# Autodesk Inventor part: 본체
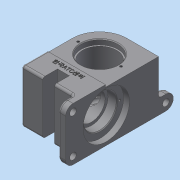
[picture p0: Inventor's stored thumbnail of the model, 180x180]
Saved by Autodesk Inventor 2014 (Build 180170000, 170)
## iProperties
Created: 2023-09
Part Number: 본체
Material: 일반
Document SubType Name: Modeling
Designer: dg
Density: 1 g/cm^3
Appearance: 기본값
Author: dg
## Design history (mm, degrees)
sketch "스케치1"
  geometry: L1 (0, 0)-(80, 0); L2 (80, 0)-(80, 106); L3 (80, 106)-(0, 106); L4 (0, 106)-(0, 0)
  constraints: 8 end point, 2 perpendicular, 1 horizontal, 1 parallel
  dimensions: "d0" = 80 distance of L2.end L3.end; "d1" = 106 distance of L3.end L1.start
extrude "돌출1" new body sketch "스케치1" distance "d2" = 33; taper "d3" = 0 deg; dims "d119" = 36, "d120" = 0
fillet "모깎기1" dims "d4" = 37
sketch "스케치2"
  geometry: L1 (80, 0)-(80, 106) reference; L2 (80, 106)-(37, 106) reference; L3 (0, 0)-(80, 0); L4 (80, 0)-(80, 34); L5 (80, 34)-(0, 34); L6 (0, 34)-(0, 0)
  constraints: 8 end point, 2 parallel, 1 horizontal, 1 perpendicular, 1 point on line
  dimensions: "d5" = 72 distance between parallel lines of L2 L5
extrude "돌출2" join sketch "스케치2" distance "d6" = 3; taper "d7" = 0 deg
sketch "스케치3"
  geometry: L1 (0, 0)-(-72, 0); L2 (-72, 0)-(-72, -20); L3 (-72, -20)-(0, -20); L4 (0, -20)-(0, 0); L5 (0, 106)-(-20, 106); L6 (-20, 106)-(-20, 126); L7 (-20, 126)-(0, 126); L8 (0, 126)-(0, 106); 2 further points
  constraints: 16 end point, 4 parallel, 2 horizontal, 2 perpendicular, 1 coincident
  dimensions: "d8" = 20 distance of L1.end L2.end; "d18" = 20 distance of L6.end L7.end; "d19" = 146 distance between parallel lines of L3 L7
extrude "돌출3" join sketch "스케치3" distance "d9" = 10; taper "d10" = 0 deg
sketch "스케치4"
  geometry: L1 (37, 106)-(80, 106) reference; L2 (80, 106)-(80, -20) reference; L3 (80, -20)-(70, -20) reference; L4 (70, -20)-(70, 0) reference; L5 (70, 0)-(0, 0) reference; L6 (0, 0)-(0, 69) reference; L7 (0, 35)-(80, 35); L8 (3, 66.5)-(3, 57.5); L9 (3, 57.5)-(15, 57.5); L10 (15, 57.5)-(15, 53.5); L11 (15, 53.5)-(60, 53.5); L12 (60, 53.5)-(60, 57.5); L13 (72, 57.5)-(72, 66.5); L14 (3, 66.5)-(0, 66.5); L15 (72, 66.5)-(80, 66.5); L16 (60, 57.5)-(72, 57.5); A1 r 37 centre (37, 69) between (37, 106) and (0, 69) reference
  constraints: 20 end point, 4 parallel, 4 point on line, 2 horizontal alignment, 2 perpendicular, 1 collinear, 1 vertical
  dimensions: "d11" = 35 distance between parallel lines of L5 L7; "d13" = 12 distance of L8.end L9.end; "d15" = 45 diameter of L9 L7; "d16" = 37 diameter of L11 L7; "d37" = 3 distance of L8.start L14.end; "d38" = 8 distance of L13.end L15.end; "d39" = 63 diameter of L15 L7; "d121" = 12 distance of L12.end L13.start
revolve "회전1" sketch "스케치4" stored, may be unused: angle "d17" = 90 deg
extrude "돌출4" join sketch "스케치3" distance "d20" = 10; taper "d21" = 0 deg
fillet "모깎기2" dims "d22" = 10
node "작업 평면1"
sketch "스케치5"
  geometry: L1 (-3, 0)-(0, 0) reference; L2 (0, 0)-(0, 72) reference; L3 (0, 72)-(69, 72) reference; L4 (69, 72)-(69, -34) reference; L5 (69, -34)-(-3, -34) reference; L6 (-3, -34)-(-3, 0) reference; L7 (0, 35)-(66, 35); L8 (0, 60)-(7, 60); L9 (7, 60)-(7, 58); L10 (7, 58)-(47, 58); L11 (47, 58)-(47, 52.5); L12 (47, 52.5)-(62, 52.5); L13 (62, 52.5)-(62, 50.5); L14 (62, 50.5)-(66, 50.5); L15 (66, 50.5)-(66, 35); C1 r 18.5 at (33, 1) reference; 1 further point
  constraints: 18 end point, 7 parallel, 2 perpendicular, 2 point on line
  dimensions: "d24" = 69 distance between parallel lines of L5 L7; "d25" = 66 distance of L7.start L7.end; "d26" = 7 distance of L8.start L8.end; "d27" = 40 distance of L9.end L10.end; "d28" = 15 distance of L11.end L12.end; "d29" = 50 diameter of L8 L7; "d30" = 46 diameter of L10 L7; "d31" = 35 diameter of L12 L7; "d32" = 31 diameter of L14 L7
revolve "회전2" sketch "스케치5" stored, may be unused: angle "d33" = 90 deg
chamfer "모따기1" distance "d34" = 1; stored, may be unused: second distance "d35" = 2, angle "d36" = 45 deg
chamfer "모따기2" distance "d41" = 1; stored, may be unused: second distance "d42" = 2, angle "d43" = 45 deg
fillet "모깎기3" dims "d44" = 0.3
fillet "모깎기4" dims "d45" = 4
fillet "모깎기5" dims "d46" = 10
hole "구멍1" diameter "d49" = 9; stored, may be unused: countersink angle "d53" = 90 deg, drill point angle "d55" = 118 deg; dims "d47" = 10, "d48" = 10, "d50" = 6, "d51" = 4, "d52" = 2, "d54" = 8
hole "구멍2" diameter "d58" = 9; stored, may be unused: countersink angle "d62" = 90 deg, drill point angle "d64" = 118 deg; dims "d56" = 10, "d57" = 10, "d59" = 6, "d60" = 4, "d61" = 2, "d63" = 8
hole "구멍3" diameter "d67" = 9; stored, may be unused: countersink angle "d71" = 90 deg, drill point angle "d73" = 118 deg; dims "d65" = 10, "d66" = 10, "d68" = 6, "d69" = 4, "d70" = 2, "d72" = 8
sketch "스케치6"
  geometry: C1 r 31.5 at (0, 0) reference; 2 further points
  constraints: 1 vertical alignment
  dimensions: "d74" = 26 distance of C1.centre point (0, 26)
hole "구멍4" sketch "스케치6" at (0, 26) diameter "d75" = 3.242; stored, may be unused: countersink angle "d79" = 90 deg, drill point angle "d81" = 118 deg; dims "d76" = 8, "d77" = 4, "d78" = 2, "d80" = 10
node "작업 평면2"
sketch "스케치7"
  geometry: A1 r 37 centre (37, 69) between (37, 106) and (0, 69) reference; 3 further points
  constraints: 2 horizontal alignment
  dimensions: "d85" = 58 distance of point (66, 69) point (8, 69); "d86" = 29 distance of A1.centre point (8, 69)
hole "구멍5" sketch "스케치7" at (8, 69), (66, 69) diameter "d87" = 3.242; stored, may be unused: countersink angle "d91" = 90 deg, drill point angle "d93" = 118 deg; dims "d88" = 8, "d89" = 4, "d90" = 2, "d92" = 10
sketch "스케치8"
  geometry: L1 (0, 0)-(70, 0) reference; L2 (29, 0)-(45, 0); L3 (45, 0)-(45, 20); L4 (45, 20)-(29, 20); L5 (29, 20)-(29, 0); C1 r 11.5 at (37, 69) reference; 2 further points
  constraints: 8 end point, 2 parallel, 1 horizontal, 1 midpoint, 1 perpendicular, 1 point on line, 1 vertical alignment
  dimensions: "d94" = 16 distance of L3.end L4.end; "d95" = 20 distance of L2.end L3.end
extrude "돌출5" cut sketch "스케치8" stored distance "d97" = 10; taper "d98" = 0 deg
sketch "스케치9"
  geometry: L1 (8, -3)-(8, -72) reference; L2 (0, -46.828)-(16, -46.828) reference; L3 (0, -46.828)-(0, -72) reference; L4 (16, -72)-(0, -72) reference; L5 (16, -46.828)-(16, -72) reference; L6 (8, -72)-(41, -72) reference; 4 further points
  constraints: 3 point on line
  dimensions: "d101" = 35 distance from line of L6 point (8, -37); "d102" = 25 distance of point (8, -12) point (8, -37); "d103" = 25 distance of point (8, -62) point (8, -37)
hole "구멍6" sketch "스케치9" at (8, -12), (8, -62) diameter "d104" = 3.242; stored, may be unused: countersink angle "d108" = 90 deg, drill point angle "d110" = 118 deg; dims "d105" = 8, "d106" = 4, "d107" = 2, "d109" = 10
sketch "스케치10"
  geometry: L1 (0, 0)-(29, 0) reference; C1 r 11.5 at (37, 69) reference; 1 further point
  constraints: 1 vertical alignment, 1 other
  dimensions: "d111" = 27 distance from line of L1 point (37, 27)
feature "엠보싱1" sketch "스케치10" dims "d0" = 80, "d1" = 106, "d7" = 0, "d112" = 0.5, "d113" = 0
fillet "모깎기6" dims "d114" = 3
fillet "모깎기7" dims "d115" = 3
fillet "모깎기8" dims "d116" = 3
fillet "모깎기9" dims "d117" = 3
fillet "모깎기10" dims "d118" = 3
fillet "모깎기11" dims "d122" = 3
fillet "모깎기12" dims "d123" = 3
node "솔리드1"
pattern_circular "원형 패턴1" dims angle "d83" = 360 deg
mirror "대칭1"
node "투영된 루프1"
node "투영된 루프2"
node "절단 모서리 투영1"
node "절단 모서리 투영2"
other parameters: "d23" = -43
